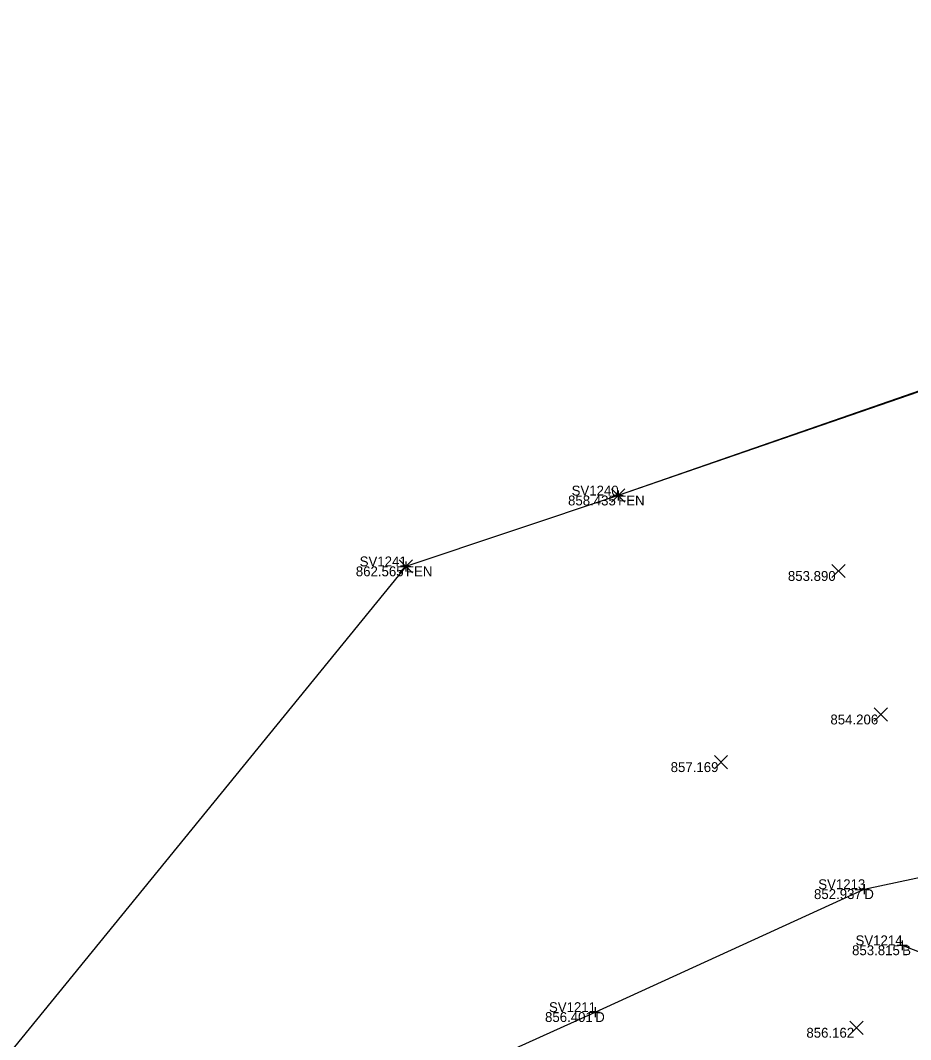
# Model space of a CAD drawing. Extents: x 2125299 to 2129212, y 713100 to 714300.
# Drawn here: x 2128168.4 to 2128258.4, y 714146 to 714249.1 of the extents above; entities that cross this region are included whole.
import ezdxf

# ---------------------------------------------------------------- set-up
doc = ezdxf.new("R2010")
doc.units = 0
for name, color, linetype in [('DR_X_Ditch', 7, 'Continuous'), ('DT_X_Terrain_Boundary', 7, 'Continuous'), ('RD_X_Fence', 7, 'Continuous'), ('RW_P_Esmt_TMP', 7, 'Continuous'), ('RW_X_Esmt_CH', 7, 'Continuous'), ('RW_X_Fee_WL', 7, 'Continuous'), ('SV_X_Break_Lines', 7, 'Continuous'), ('SV_X_Mon_Cells_Found', 7, 'Continuous'), ('SV_X_Text_Elevation', 7, 'Continuous')]:
    doc.layers.add(name, color=color, linetype=linetype)

msp = doc.modelspace()

# ---------------------------------------------------------------- linework, layer by layer
at = {"layer": 'DR_X_Ditch'}
msp.add_lwpolyline([(2128126.02, 714119.43), (2128165.52, 714127.08), (2128190.47, 714132.5), (2128226.54, 714148.8), (2128253.76, 714161.24), (2128264.19, 714163.45), (2128277.88, 714165.58), (2128280.71, 714165.85)], dxfattribs=at)
at = {"layer": 'DT_X_Terrain_Boundary'}
msp.add_lwpolyline([(2128442.63, 714160.2), (2128404.43, 714186.27), (2128371.88, 714249.15), (2128341.8, 714239.46), (2128307.19, 714228.08), (2128286.83, 714221.22), (2128228.86, 714201.07), (2128207.39, 714193.9), (2128150.55, 714124.18), (2128126.02, 714119.43), (2128120.14, 714107.52), (2128111.88, 714086.22), (2128106.87, 714068.79), (2128101.83, 714061.27), (2128102.4, 714047.83), (2128092.73, 714045.3), (2128083.06, 714042.76), (2128073.38, 714040.23), (2128063.71, 714037.7), (2128054.04, 714035.16), (2128044.36, 714032.63), (2128034.69, 714030.09), (2128025.02, 714027.56)], dxfattribs=at)
at = {"layer": 'RD_X_Fence'}
msp.add_lwpolyline([(2128371.88, 714249.15), (2128341.8, 714239.46), (2128307.19, 714228.08), (2128228.86, 714201.07), (2128207.39, 714193.9)], dxfattribs=at)
at = {"layer": 'SV_X_Break_Lines'}
msp.add_lwpolyline([(2128257.59, 714155.56), (2128263.49, 714153.24), (2128269.27, 714148.53), (2128290.13, 714150.8), (2128296.99, 714153.38), (2128311.86, 714153.9), (2128347.24, 714163.06), (2128380.91, 714169.43), (2128405.4, 714183.35)], dxfattribs=at)
at = {"layer": 'SV_X_Mon_Cells_Found'}
for p, q in [((2128228.86, 714201.57), (2128228.86, 714200.57)), ((2128228.36, 714201.07), (2128229.36, 714201.07)), ((2128228.86, 714201.07), (2128228.86, 714201.07)), ((2128207.39, 714194.4), (2128207.39, 714193.4)), ((2128206.89, 714193.9), (2128207.89, 714193.9)), ((2128207.39, 714193.9), (2128207.39, 714193.9)), ((2128253.26, 714161.24), (2128254.26, 714161.24)), ((2128253.76, 714161.74), (2128253.76, 714160.74)), ((2128253.76, 714161.24), (2128253.76, 714161.24)), ((2128257.09, 714155.56), (2128258.09, 714155.56)), ((2128257.59, 714156.06), (2128257.59, 714155.06)), ((2128257.59, 714155.56), (2128257.59, 714155.56)), ((2128226.54, 714149.3), (2128226.54, 714148.3)), ((2128226.04, 714148.8), (2128227.04, 714148.8)), ((2128226.54, 714148.8), (2128226.54, 714148.8))]:
    msp.add_line(p, q, dxfattribs=at)
at = {"layer": 'SV_X_Text_Elevation'}
for p, q in [((2128228.2, 714200.4), (2128229.53, 714201.74)), ((2128228.2, 714201.74), (2128229.53, 714200.4)), ((2128206.72, 714193.24), (2128208.06, 714194.57)), ((2128206.72, 714194.57), (2128208.06, 714193.24)), ((2128250.48, 714192.76), (2128251.81, 714194.09)), ((2128250.48, 714194.09), (2128251.81, 714192.76)), ((2128254.76, 714178.25), (2128256.1, 714179.58)), ((2128254.76, 714179.58), (2128256.1, 714178.25)), ((2128238.59, 714173.43), (2128239.92, 714174.76)), ((2128238.59, 714174.76), (2128239.92, 714173.43)), ((2128252.31, 714146.54), (2128253.64, 714147.87)), ((2128252.31, 714147.87), (2128253.64, 714146.54))]:
    msp.add_line(p, q, dxfattribs=at)

# ---------------------------------------------------------------- texts
at = {"layer": 'RW_P_Esmt_TMP'}
for s, p in [('FEN', (2128228.86, 714200.07)), ('FEN', (2128207.39, 714192.9)), ('D', (2128253.76, 714160.24)), ('B', (2128257.59, 714154.56)), ('D', (2128226.54, 714147.8))]:
    msp.add_text(s, height=1, dxfattribs=at).set_placement(p)
at = {"layer": 'RW_X_Esmt_CH'}
for s, p in [('SV1240', (2128224.15, 714201.07)), ('SV1241', (2128202.71, 714193.9)), ('SV1213', (2128249.1, 714161.24)), ('SV1214', (2128252.87, 714155.56)), ('SV1211', (2128221.86, 714148.8))]:
    msp.add_text(s, height=1, dxfattribs=at).set_placement(p)
at = {"layer": 'RW_X_Fee_WL'}
for s, p in [('858.435', (2128223.79, 714200.07)), ('858.435', (2128223.79, 714200.07)), ('862.565', (2128202.32, 714192.9)), ('862.565', (2128202.32, 714192.9)), ('853.890', (2128246.03, 714192.43)), ('854.206', (2128250.33, 714177.91)), ('857.169', (2128234.17, 714173.09)), ('852.937', (2128248.67, 714160.24)), ('853.815', (2128252.52, 714154.56)), ('856.401', (2128221.46, 714147.8)), ('856.162', (2128247.9, 714146.21))]:
    msp.add_text(s, height=1, dxfattribs=at).set_placement(p)

doc.saveas('drawing.dxf')
